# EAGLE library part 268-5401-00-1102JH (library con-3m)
Zero Insertion Force Socked Source: http://www.3M.com/ehpd
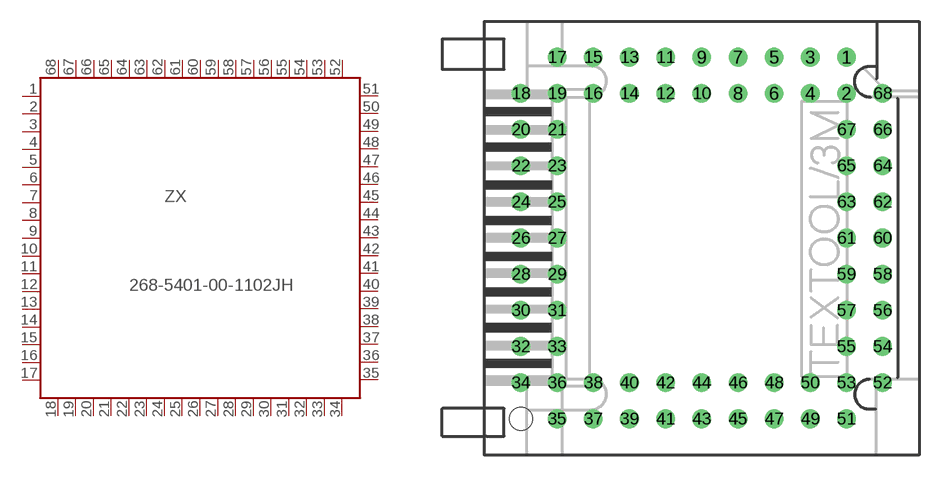
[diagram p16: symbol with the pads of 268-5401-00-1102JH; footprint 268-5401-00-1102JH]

Designator prefix ZX

## 268-5401-00-1102JH (MPN: 268-5401-00-1102JH; OC_FARNELL: unknown; OC_NEWARK: 42M9902)  [268-5401-00-1102JH]
1  1  pas
2  2  pas
3  3  pas
4  4  pas
5  5  pas
6  6  pas
7  7  pas
8  8  pas
9  9  pas
10  10  pas
11  11  pas
12  12  pas
13  13  pas
14  14  pas
15  15  pas
16  16  pas
17  17  pas
18  18  pas
19  19  pas
20  20  pas
21  21  pas
22  22  pas
23  23  pas
24  24  pas
25  25  pas
26  26  pas
27  27  pas
28  28  pas
29  29  pas
30  30  pas
31  31  pas
32  32  pas
33  33  pas
34  34  pas
35  35  pas
36  36  pas
37  37  pas
38  38  pas
39  39  pas
40  40  pas
41  41  pas
42  42  pas
43  43  pas
44  44  pas
45  45  pas
46  46  pas
47  47  pas
48  48  pas
49  49  pas
50  50  pas
51  51  pas
52  52  pas
53  53  pas
54  54  pas
55  55  pas
56  56  pas
57  57  pas
58  58  pas
59  59  pas
60  60  pas
61  61  pas
62  62  pas
63  63  pas
64  64  pas
65  65  pas
66  66  pas
67  67  pas
68  68  pas

## Footprint 268-5401-00-1102JH (pad centres in mm)
OEM LCC Sockets 68 pol. Farnell Best. Nr. 4665417 Source: http://www.3M.com/ehpd
drill 0.8 pad 1.27 round: 1 10.16,12.7; 2 10.16,10.16; 3 7.62,12.7; 4 7.62,10.16; 5 5.08,12.7; 6 5.08,10.16; 7 2.54,12.7; 8 2.54,10.16; 9 0,12.7; 10 0,10.16; 11 -2.54,12.7; 12 -2.54,10.16; 13 -5.08,12.7; 14 -5.08,10.16; 15 -7.62,12.7; 16 -7.62,10.16; 17 -10.16,12.7; 18 -12.7,10.16; 19 -10.16,10.16; 20 -12.7,7.62; 21 -10.16,7.62; 22 -12.7,5.08; 23 -10.16,5.08; 24 -12.7,2.54; 25 -10.16,2.54; 26 -12.7,0; 27 -10.16,0; 28 -12.7,-2.54; 29 -10.16,-2.54; 30 -12.7,-5.08; 31 -10.16,-5.08; 32 -12.7,-7.62; 33 -10.16,-7.62; 34 -12.7,-10.16; 35 -10.16,-12.7; 36 -10.16,-10.16; 37 -7.62,-12.7; 38 -7.62,-10.16; 39 -5.08,-12.7; 40 -5.08,-10.16; 41 -2.54,-12.7; 42 -2.54,-10.16; 43 0,-12.7; 44 0,-10.16; 45 2.54,-12.7; 46 2.54,-10.16; 47 5.08,-12.7; 48 5.08,-10.16; 49 7.62,-12.7; 50 7.62,-10.16; 51 10.16,-12.7; 52 12.7,-10.16; 53 10.16,-10.16; 54 12.7,-7.62; 55 10.16,-7.62; 56 12.7,-5.08; 57 10.16,-5.08; 58 12.7,-2.54; 59 10.16,-2.54; 60 12.7,0; 61 10.16,0; 62 12.7,2.54; 63 10.16,2.54; 64 12.7,5.08; 65 10.16,5.08; 66 12.7,7.62; 67 10.16,7.62; 68 12.7,10.16
hole 1.6 at -12.7,-12.7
